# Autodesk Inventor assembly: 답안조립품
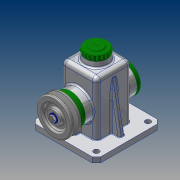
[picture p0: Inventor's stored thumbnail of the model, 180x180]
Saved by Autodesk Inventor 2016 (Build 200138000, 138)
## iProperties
Created: 2018-10
Part Number: 답안조립품
Material: 일반
Document SubType Name: Assembly
Designer: user
Author: user
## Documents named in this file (14)
- C:\Users\user\Desktop\481016V1007\답안조립품.iam
- C:\Users\user\Desktop\481016V1007\본체.ipt
- C:\Users\user\Desktop\481016V1007\베어링 15 x 35 x 11.ipt
- C:\Users\user\Desktop\481016V1007\앞커버.ipt
- C:\Users\user\Desktop\481016V1007\오일실 15 25 7.ipt
- C:\Users\user\Desktop\481016V1007\축.ipt
- C:\Users\user\Desktop\481016V1007\멈춤링 15 x 1.ipt
- C:\Users\user\Desktop\481016V1007\뒤커버.ipt
- C:\Users\user\Desktop\481016V1007\키 5 x 5 x 14.ipt
- C:\Users\user\Desktop\481016V1007\V-벨트풀리.ipt
- C:\Users\user\Desktop\481016V1007\와셔.ipt
- C:\Users\user\Desktop\481016V1007\볼트 M6 x 12.ipt
- C:\Users\user\Desktop\481016V1007\볼트 M4 x 10.ipt
- C:\Users\user\Desktop\481016V1007\상부캡.ipt
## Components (1 placed, 1 different names)
1. V-벨트풀리:1
